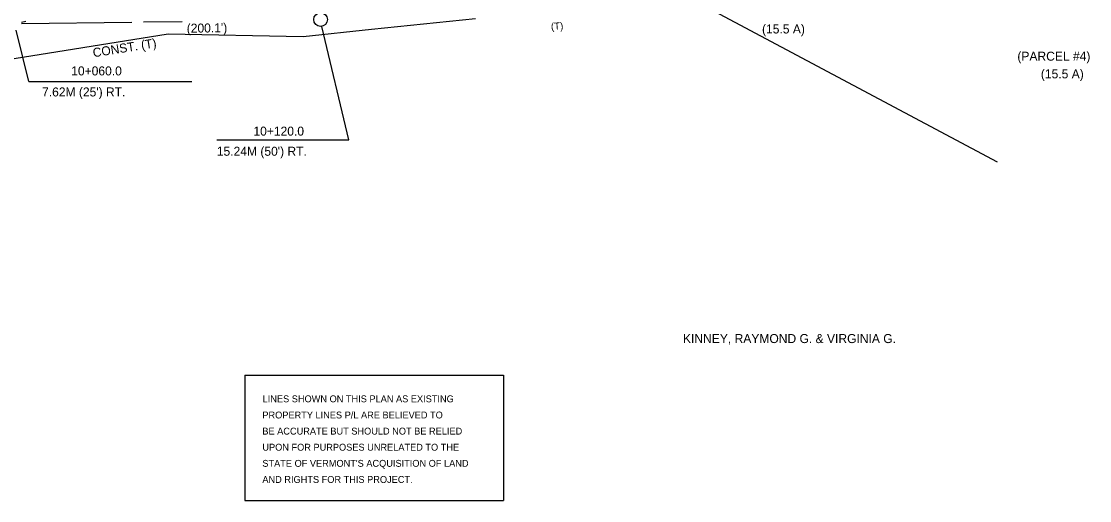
# Model space of a CAD drawing. Extents: x 624 to 1448, y 1599 to 1865.
# Drawn here: x 922.4 to 1133.7, y 1598.6 to 1693.4 of the extents above; entities that cross this region are included whole.
import ezdxf

# ---------------------------------------------------------------- set-up
doc = ezdxf.new("R2010")
doc.units = 0
for name, color, linetype in [('C_I', 7, 'Continuous'), ('C_TIC', 7, 'Continuous'), ('L_A', 7, 'Continuous'), ('L_C', 7, 'Continuous'), ('L_I', 7, 'Continuous'), ('Level 30', 7, 'Continuous'), ('ODIML_P', 7, 'Continuous')]:
    doc.layers.add(name, color=color, linetype=linetype)

msp = doc.modelspace()

# ---------------------------------------------------------------- linework, layer by layer
at = {"layer": 'C_TIC'}
for p, q in [((922.43, 1693), (944.26, 1693.28)), ((946.58, 1693.31), (954.21, 1693.41))]:
    msp.add_line(p, q, dxfattribs=at)
at = {"layer": 'L_C'}
for p, q in [((923.9, 1681.52), (921.37, 1691.66)), ((987.17, 1669.98), (981.87, 1692.43)), ((923.9, 1681.52), (956.11, 1681.52)), ((961.05, 1669.98), (987.17, 1669.98))]:
    msp.add_line(p, q, dxfattribs=at)
at = {"layer": 'L_I'}
msp.add_line((1047.79, 1701.7), (1115.44, 1665.62), dxfattribs=at)
msp.add_circle((981.6, 1693.78), 1.35, dxfattribs=at)
at = {"layer": 'Level 30'}
for p, q in [((991.67, 1691.85), (1012.27, 1694)), ((912.99, 1684.83), (951.45, 1690.95)), ((951.45, 1690.95), (978.14, 1690.45))]:
    msp.add_line(p, q, dxfattribs=at)
msp.add_lwpolyline([(978.14, 1690.45), (991.67, 1691.85)], dxfattribs=at)
at = {"layer": 'ODIML_P'}
for p, q in [((966.64, 1623.41), (1017.81, 1623.41)), ((966.64, 1623.41), (966.64, 1598.62)), ((1017.81, 1623.41), (1017.81, 1598.62)), ((966.64, 1598.62), (1017.81, 1598.62))]:
    msp.add_line(p, q, dxfattribs=at)
msp.add_lwpolyline([(922.41, 1693.28), (923.31, 1693.43)], dxfattribs=at)

# ---------------------------------------------------------------- texts
at = {"layer": 'C_I'}
for s, height, rotation, p in [("(200.1')", 1.783, 0.7439, (955.13, 1691.17)), ('(T)', 1.426, 4.4571, (1027.22, 1691.68)), ('CONST. (T)', 1.783, 9.0541, (936.68, 1686.31))]:
    msp.add_text(s, height=height, rotation=rotation, dxfattribs=at).set_placement(p)
at = {"layer": 'L_A'}
for s, p in [('(15.5 A)', (1068.92, 1691.03)), ('(PARCEL #4)', (1119.43, 1685.64)), ('(15.5 A)', (1124.08, 1682.15)), ('KINNEY, RAYMOND G. & VIRGINIA G.', (1053.29, 1629.79))]:
    msp.add_text(s, height=1.783, dxfattribs=at).set_placement(p)
at = {"layer": 'L_C'}
for s, p in [('10+060.0', (932.27, 1682.73)), ("7.62M (25') RT.", (926.5, 1678.57)), ('10+120.0', (968.31, 1670.82)), ("15.24M (50') RT.", (961.07, 1666.84))]:
    msp.add_text(s, height=1.783, dxfattribs=at).set_placement(p)
at = {"layer": 'ODIML_P'}
for s, p in [('LINES SHOWN ON THIS PLAN AS EXISTING', (970.13, 1618.08)), ('BE ACCURATE BUT SHOULD NOT BE RELIED', (970.08, 1611.69)), ('UPON FOR PURPOSES UNRELATED TO THE', (970.08, 1608.51)), ("STATE OF VERMONT'S ACQUISITION OF LAND", (970.08, 1605.32)), ('AND RIGHTS FOR THIS PROJECT.', (970.08, 1602.13))]:
    msp.add_text(s, height=1.3608, dxfattribs=at).set_placement(p)
msp.add_text('PROPERTY LINES P/L ARE BELIEVED TO', height=1.3608, rotation=0.0007, dxfattribs=at).set_placement((970.08, 1614.88))

doc.saveas('drawing.dxf')
